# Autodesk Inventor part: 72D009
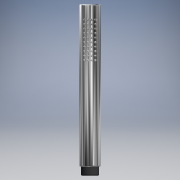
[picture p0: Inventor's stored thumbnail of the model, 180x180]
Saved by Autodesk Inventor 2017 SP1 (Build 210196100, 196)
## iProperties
Created: 2019-04
Part Number: 72D009
Material: Generico
Document SubType Name: Modeling
Designer: CIANI A.
Density: 1 g/cm^3
Appearance: Default
Author: CIANI A.
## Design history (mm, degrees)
feature "Base1"
node "Solido1"
node "Solido2"
